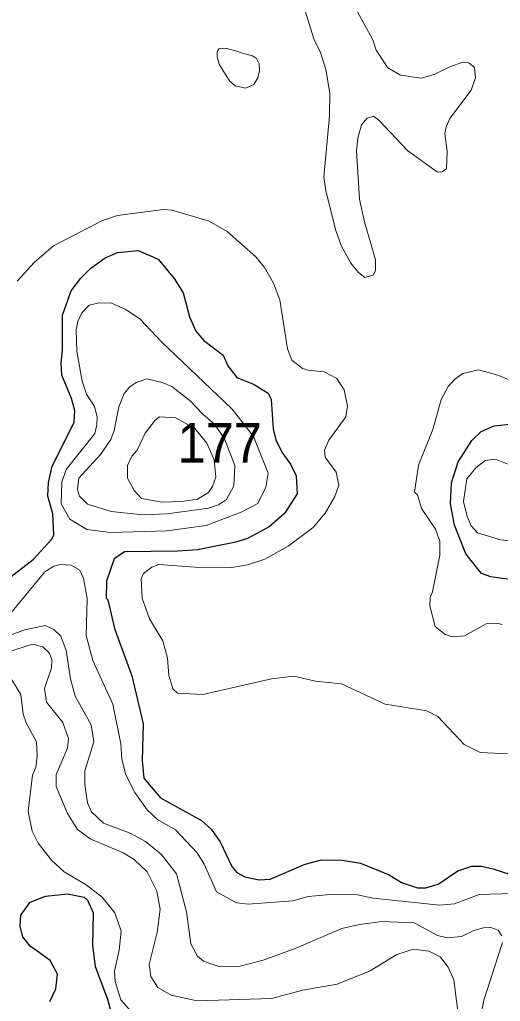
# Model space of a CAD drawing. Extents: x 673.6 to 698.9, y 7012 to 7040.1.
# Drawn here: x 678.917 to 679.882, y 7020.23 to 7022.201 of the extents above; entities that cross this region are included whole.
import ezdxf

# ---------------------------------------------------------------- set-up
doc = ezdxf.new("R2010")
doc.units = 0
doc.header["$LTSCALE"] = 0.032
doc.layers.add('1', color=7, linetype='Continuous', lineweight=25)
doc.layers.add('2', color=7, linetype='Continuous', lineweight=13)
doc.layers.add('21', color=7, linetype='Continuous')

msp = doc.modelspace()

# ---------------------------------------------------------------- linework, layer by layer
at = {"layer": '1'}
for points in [[(678.8917, 7021.0762), (678.9442, 7021.1173), (678.9819, 7021.1581), (678.9855, 7021.1664), (678.984, 7021.2087), (678.9735, 7021.2445), (678.9748, 7021.272), (678.9821, 7021.3046), (679.0265, 7021.392), (679.0278, 7021.4165), (679.0215, 7021.4403), (679.0019, 7021.4876), (679.0002, 7021.5117), (679.0035, 7021.539), (679.0035, 7021.6079), (679.0206, 7021.6568), (679.0399, 7021.6822), (679.0602, 7021.7024), (679.0886, 7021.7227), (679.1136, 7021.7336), (679.155, 7021.7377), (679.1951, 7021.7201), (679.2272, 7021.6815), (679.2456, 7021.6527), (679.2583, 7021.6043), (679.271, 7021.5754), (679.287, 7021.557), (679.3255, 7021.5273), (679.3355, 7021.506), (679.353, 7021.4828), (679.3864, 7021.469)], [(679.3864, 7021.469), (679.4163, 7021.4511), (679.4225, 7021.4383), (679.4259, 7021.3795), (679.4313, 7021.3573), (679.4435, 7021.3325)], [(679.9198, 7021.0743), (679.8631, 7021.0823), (679.8444, 7021.089), (679.8133, 7021.1288), (679.7904, 7021.1864), (679.7824, 7021.2287), (679.7842, 7021.2714), (679.7979, 7021.3134), (679.8249, 7021.3561), (679.8436, 7021.3739), (679.8699, 7021.3853), (679.9069, 7021.3893)], [(679.4435, 7021.3325), (679.4613, 7021.3085), (679.4722, 7021.285), (679.4747, 7021.2489), (679.4487, 7021.2094), (679.4182, 7021.1827), (679.3744, 7021.1591), (679.3514, 7021.1518), (679.2745, 7021.1365), (679.2349, 7021.1338), (679.1276, 7021.1325), (679.1068, 7021.1186), (679.0914, 7021.0738), (679.0906, 7021.0397), (679.0939, 7021.0361), (679.1078, 7020.9784), (679.1421, 7020.8835), (679.165, 7020.7872), (679.1629, 7020.7134), (679.1666, 7020.6779), (679.2001, 7020.6387), (679.282, 7020.5932), (679.3018, 7020.5757), (679.3196, 7020.5499), (679.3434, 7020.5006), (679.3535, 7020.4887), (679.3693, 7020.4802), (679.3979, 7020.474), (679.4205, 7020.4755), (679.4907, 7020.5051), (679.5232, 7020.514), (679.5648, 7020.5133), (679.6019, 7020.5075), (679.6592, 7020.4837), (679.6839, 7020.4682), (679.716, 7020.4575), (679.7331, 7020.4575), (679.7577, 7020.4649), (679.7969, 7020.4917), (679.8252, 7020.5011), (679.8449, 7020.501), (679.8683, 7020.496), (679.939, 7020.4723)], [(678.9777, 7020.2295), (678.99, 7020.255), (678.9934, 7020.2841), (678.9786, 7020.312), (678.9381, 7020.3405), (678.9235, 7020.3597), (678.918, 7020.3802), (678.9197, 7020.4028), (678.9382, 7020.4293), (678.9693, 7020.4411), (679.0129, 7020.4459), (679.0469, 7020.4392), (679.0535, 7020.4328), (679.065, 7020.4077), (679.0635, 7020.342), (679.0691, 7020.3001), (679.0937, 7020.2343), (679.1071, 7020.1839)]]:
    msp.add_lwpolyline(points, dxfattribs=at)
at = {"layer": '2'}
for points in [[(679.5955, 7022.2167), (679.6263, 7022.1609), (679.6331, 7022.1401), (679.6563, 7022.1047), (679.6819, 7022.0896), (679.7231, 7022.0837), (679.7495, 7022.0908), (679.7807, 7022.1067), (679.8068, 7022.1156), (679.8191, 7022.1148), (679.8306, 7022.1048), (679.8325, 7022.0845), (679.824, 7022.0593), (679.7813, 7022.003), (679.7736, 7021.986), (679.771, 7021.9717), (679.7758, 7021.937), (679.7742, 7021.9019), (679.7651, 7021.8956), (679.7565, 7021.8948), (679.6964, 7021.938), (679.6386, 7021.9991), (679.6277, 7022.0071), (679.6149, 7022.0031), (679.6035, 7021.9903), (679.596, 7021.9632), (679.5935, 7021.9378), (679.5993, 7021.8407), (679.6093, 7021.7955), (679.6319, 7021.7189), (679.632, 7021.6971), (679.6271, 7021.688), (679.6102, 7021.6836), (679.5975, 7021.6933), (679.582, 7021.7122), (679.563, 7021.7476), (679.5521, 7021.7779), (679.5318, 7021.8577), (679.5278, 7021.8852), (679.5392, 7022.0082), (679.54, 7022.0536), (679.5322, 7022.1009), (679.5211, 7022.1355), (679.5078, 7022.1625), (679.4887, 7022.2249)], [(679.5581, 7021.2665), (679.5527, 7021.2922), (679.5305, 7021.3224), (679.5294, 7021.3369), (679.5383, 7021.357), (679.5723, 7021.4033), (679.5753, 7021.4251), (679.5689, 7021.458), (679.554, 7021.4803), (679.5286, 7021.4937), (679.4966, 7021.497), (679.4854, 7021.501), (679.4637, 7021.5176), (679.4552, 7021.5401), (679.4399, 7021.6384), (679.4272, 7021.6723), (679.4088, 7021.7033), (679.3916, 7021.7251), (679.3339, 7021.776), (679.298, 7021.7967), (679.2233, 7021.8184), (679.2057, 7021.8199), (679.1139, 7021.8077), (679.0835, 7021.7981), (678.9854, 7021.7468), (678.9461, 7021.7134), (678.912, 7021.6759)], [(679.9218, 7021.4692), (679.8773, 7021.4875), (679.8383, 7021.4979), (679.8074, 7021.4905), (679.791, 7021.4791), (679.7774, 7021.4646), (679.7634, 7021.4383), (679.7466, 7021.3785), (679.7181, 7021.3065), (679.7103, 7021.2524), (679.7158, 7021.247), (679.7244, 7021.2194), (679.7523, 7021.1783), (679.7611, 7021.154), (679.761, 7021.1258)], [(679.4094, 7021.1181), (679.4564, 7021.144), (679.5066, 7021.1817), (679.5308, 7021.2099), (679.5501, 7021.2435), (679.5581, 7021.2665)], [(679.761, 7021.1258), (679.7463, 7021.0521), (679.7414, 7021.0409), (679.7406, 7021.024), (679.7518, 7020.9824), (679.7713, 7020.9668)], [(679.9087, 7020.4467), (679.84, 7020.4445), (679.7902, 7020.4255), (679.7606, 7020.423), (679.6272, 7020.437), (679.5955, 7020.4434), (679.5479, 7020.4452), (679.4966, 7020.4402), (679.4659, 7020.432), (679.3762, 7020.4247), (679.3527, 7020.4278), (679.3127, 7020.4498), (679.2877, 7020.5051), (679.2735, 7020.5284), (679.2301, 7020.5744), (679.1939, 7020.595), (679.1729, 7020.6142), (679.1482, 7020.6494), (679.1302, 7020.685), (679.1225, 7020.7159), (679.1201, 7020.7467), (679.1043, 7020.8264), (679.0642, 7020.9143), (679.051, 7020.9648), (679.0527, 7021.0386), (679.0453, 7021.0787), (679.038, 7021.0956), (679.0205, 7021.1055), (678.9994, 7021.1073), (678.9859, 7021.1036), (678.9675, 7021.0926), (678.9019, 7021.0125)], [(679.9002, 7020.727), (679.842, 7020.7295), (679.8095, 7020.7453), (679.7568, 7020.8017), (679.7345, 7020.8132), (679.6513, 7020.8264), (679.5636, 7020.8675), (679.511, 7020.8725), (679.4676, 7020.883), (679.4226, 7020.8773), (679.2848, 7020.8462), (679.2343, 7020.8489), (679.225, 7020.8576), (679.2164, 7020.8842), (679.2139, 7020.919), (679.2046, 7020.9541), (679.1778, 7020.9979), (679.1632, 7021.0398), (679.1613, 7021.0783), (679.1658, 7021.089), (679.1824, 7021.1015), (679.1964, 7021.1074), (679.2694, 7021.1018), (679.3424, 7021.1009), (679.3745, 7021.1066), (679.4094, 7021.1181)], [(678.8492, 7020.9481), (678.9278, 7020.976), (678.9681, 7020.9847), (678.9859, 7020.9764), (679, 7020.9632), (679.0108, 7020.9341), (679.0192, 7020.8776), (679.0287, 7020.8427), (679.061, 7020.785), (679.0659, 7020.7511), (679.048, 7020.6928), (679.0479, 7020.6651), (679.0536, 7020.6285), (679.0616, 7020.6107), (679.0854, 7020.5875), (679.1392, 7020.5679), (679.17, 7020.5507), (679.2012, 7020.5251), (679.2324, 7020.4858), (679.2524, 7020.4098), (679.2607, 7020.3455), (679.2744, 7020.3208), (679.2863, 7020.3103), (679.317, 7020.2998), (679.3601, 7020.3005), (679.4064, 7020.3122), (679.4705, 7020.336), (679.5638, 7020.3761), (679.5997, 7020.3843), (679.6453, 7020.3901), (679.7095, 7020.3875), (679.7562, 7020.3622), (679.7756, 7020.3573), (679.8045, 7020.3599), (679.829, 7020.3719), (679.8485, 7020.3777), (679.8635, 7020.3784), (679.8783, 7020.3725), (679.8851, 7020.3612)], [(679.7713, 7020.9668), (679.7869, 7020.9621), (679.8102, 7020.9637), (679.8542, 7020.9877), (679.8756, 7020.9892), (679.886, 7020.9866)], [(679.708, 7020.3349), (679.6744, 7020.3237), (679.6207, 7020.2911), (679.5549, 7020.2641), (679.4858, 7020.2522), (679.423, 7020.2355), (679.2739, 7020.2307), (679.2215, 7020.2425), (679.1944, 7020.2574), (679.1803, 7020.2797), (679.1769, 7020.3038), (679.1931, 7020.368), (679.199, 7020.4147), (679.1923, 7020.4508), (679.1729, 7020.49), (679.1474, 7020.5148), (679.125, 7020.5281), (679.059, 7020.5562), (679.0333, 7020.5747), (679.0134, 7020.607), (678.9904, 7020.6613), (678.9904, 7020.6856), (679.0131, 7020.7383), (679.0149, 7020.7578), (679.0037, 7020.7897), (678.9713, 7020.8305), (678.9673, 7020.858), (678.9811, 7020.8993), (678.982, 7020.9154), (678.9772, 7020.9289), (678.964, 7020.9418), (678.9431, 7020.9471), (678.8716, 7020.9241)], [(678.9015, 7020.8757), (678.9194, 7020.8463), (678.9244, 7020.8065), (678.9304, 7020.7891)], [(678.9304, 7020.7891), (678.9508, 7020.7512), (678.9525, 7020.7221), (678.9493, 7020.6997), (678.9427, 7020.6843), (678.9345, 7020.612)], [(678.9345, 7020.612), (678.9425, 7020.5717), (678.9543, 7020.5475), (678.981, 7020.5135), (679.0068, 7020.4898), (679.0505, 7020.4636), (679.083, 7020.4393), (679.1084, 7020.4074), (679.1208, 7020.3706), (679.1168, 7020.3325), (679.1078, 7020.2905), (679.109, 7020.2696), (679.1204, 7020.233), (679.1456, 7020.2043)], [(679.7996, 7020.1886), (679.7893, 7020.273), (679.7779, 7020.2987), (679.7613, 7020.3191), (679.7385, 7020.3304), (679.708, 7020.3349)], [(679.8867, 7020.3482), (679.8494, 7020.2324), (679.8425, 7020.1964), (679.8425, 7020.1482), (679.8508, 7020.1022), (679.8628, 7020.0734), (679.8658, 7020.0575), (679.877, 7020.0364), (679.8942, 7019.9651)]]:
    msp.add_lwpolyline(points, dxfattribs=at)
for points in [[(679.3176, 7022.1119), (679.3302, 7022.0911), (679.3391, 7022.0777), (679.3496, 7022.068), (679.3704, 7022.0635), (679.3875, 7022.071), (679.3957, 7022.0844), (679.3987, 7022.0985), (679.398, 7022.1127), (679.3928, 7022.1231), (679.3846, 7022.1283), (679.3667, 7022.1335), (679.3503, 7022.1387), (679.3332, 7022.1432), (679.3235, 7022.144), (679.3168, 7022.1425), (679.3153, 7022.1395), (679.3138, 7022.1358), (679.3138, 7022.1268)], [(679.0522, 7021.1777), (679.0998, 7021.1716), (679.2124, 7021.1749), (679.2916, 7021.1857), (679.3618, 7021.2119), (679.3955, 7021.2293), (679.4115, 7021.2622), (679.4159, 7021.2904), (679.3864, 7021.3644), (679.3442, 7021.4192), (679.2019, 7021.5541), (679.159, 7021.5995), (679.1306, 7021.6192), (679.1013, 7021.6318), (679.0767, 7021.6325), (679.0564, 7021.628), (679.0422, 7021.6123), (679.034, 7021.5952), (679.0305, 7021.578), (679.0322, 7021.5353), (679.0428, 7021.4752), (679.0516, 7021.4492), (679.0673, 7021.4241), (679.0725, 7021.4036), (679.0724, 7021.3874), (679.068, 7021.3701), (679.0106, 7021.2977), (679.0021, 7021.2726), (679.0002, 7021.229), (679.018, 7021.1979)], [(679.0794, 7021.3279), (679.1002, 7021.3578), (679.1069, 7021.3763), (679.116, 7021.4235), (679.1272, 7021.4507), (679.1383, 7021.464), (679.1508, 7021.4723), (679.1727, 7021.4797), (679.203, 7021.4729), (679.2227, 7021.4645), (679.2593, 7021.4359), (679.2847, 7021.4088), (679.3091, 7021.3885), (679.3286, 7021.3592), (679.3494, 7021.3059), (679.3471, 7021.2653), (679.3328, 7021.2375), (679.3163, 7021.2269), (679.2964, 7021.2201), (679.2133, 7021.2086), (679.165, 7021.207), (679.1008, 7021.2135), (679.0531, 7021.2281), (679.0368, 7021.245), (679.0331, 7021.2582), (679.0362, 7021.2805)], [(679.1423, 7021.3247), (679.1336, 7021.3062), (679.1337, 7021.2803), (679.147, 7021.2556), (679.1616, 7021.2398), (679.2033, 7021.2324), (679.2428, 7021.2333), (679.274, 7021.238), (679.2965, 7021.2519), (679.3047, 7021.2638), (679.3114, 7021.2822), (679.3078, 7021.317), (679.2933, 7021.351), (679.2688, 7021.3803), (679.23, 7021.4016), (679.1977, 7021.4033), (679.1895, 7021.397), (679.1693, 7021.3708), (679.153, 7021.3368)], [(679.9151, 7021.1534), (679.8824, 7021.1568), (679.8367, 7021.171), (679.8237, 7021.1847), (679.8155, 7021.2033), (679.8087, 7021.2337), (679.8154, 7021.2789), (679.8334, 7021.3014), (679.852, 7021.3159), (679.8725, 7021.3186), (679.9027, 7021.3063), (679.9362, 7021.2983), (679.9823, 7021.2942), (680.0106, 7021.2827), (680.0349, 7021.2609), (680.0691, 7021.206), (680.0759, 7021.1799), (680.0758, 7021.1489), (680.067, 7021.1357), (680.0496, 7021.1243), (680.0154, 7021.1241), (679.952, 7021.1395)]]:
    msp.add_lwpolyline(points, close=True, dxfattribs=at)

# ---------------------------------------------------------------- texts
at = {"layer": '21', "width": 0.95}
msp.add_text('177', height=0.08, dxfattribs=at).set_placement((679.2341, 7021.3115))

doc.saveas('drawing.dxf')
